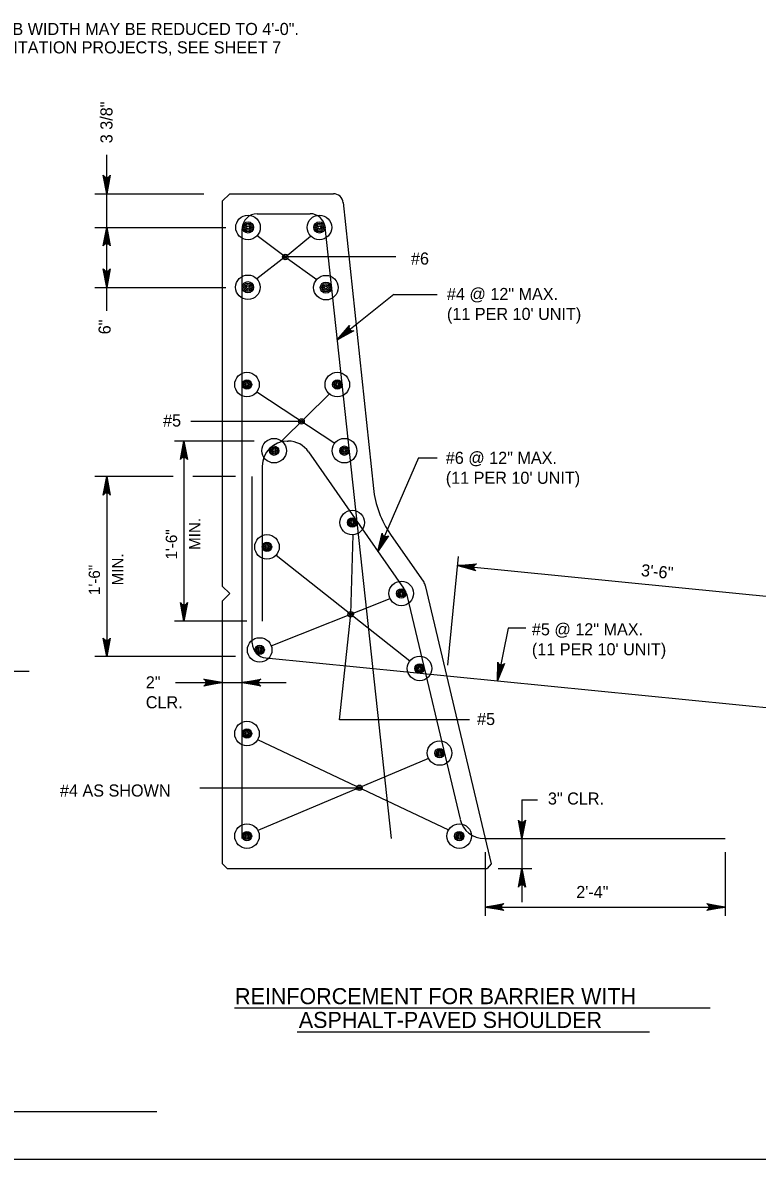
# Model space of a CAD drawing. Extents: x 638167 to 640248, y 296544 to 298920.
# Drawn here: x 638562.8 to 638749.3, y 297153.5 to 297442.2 of the extents above; entities that cross this region are included whole.
import ezdxf

# ---------------------------------------------------------------- set-up
doc = ezdxf.new("R2010")
doc.units = 0
for name, color, linetype in [('1', 7, 'Continuous'), ('50', 7, 'Continuous'), ('57', 7, 'Continuous')]:
    doc.layers.add(name, color=color, linetype=linetype)

# ---------------------------------------------------------------- blocks, each defined once
blk = doc.blocks.new('DIMDOT')
at = {"layer": '57'}
for radius in [2, 1]:
    blk.add_circle((0, 0), radius, dxfattribs=at)
blk = doc.blocks.new('BAR')
at = {"layer": '50'}
for radius in [2, 1.5, 1, 0.5]:
    blk.add_circle((0, 0), radius, dxfattribs=at)

msp = doc.modelspace()

# ---------------------------------------------------------------- linework, layer by layer
at = {"layer": '1'}
for p, q in [((638584.13, 297369), (638584.13, 297408.62)), ((638581.1, 297398.78), (638608.76, 297398.78)), ((638615.37, 297398.78), (638613.46, 297396.88)), ((638615.37, 297398.78), (638641.66, 297398.78)), ((638613.46, 297396.88), (638613.46, 297299.09)), ((638644.18, 297396.51), (638651.84, 297323.92)), ((638622.35, 297393.7), (638635.76, 297393.7)), ((638581.1, 297390.21), (638614.34, 297390.21)), ((638618.54, 297234.95), (638618.54, 297389.89)), ((638639.54, 297390.3), (638656.32, 297234.95)), ((638629.45, 297382.71), (638622.3, 297388.11)), ((638629.47, 297382.74), (638635.9, 297388.01)), ((638629.45, 297382.71), (638622.27, 297377.12)), ((638657.56, 297382.71), (638629.45, 297382.71)), ((638629.45, 297382.71), (638637.43, 297376.99)), ((638581.1, 297374.97), (638614.34, 297374.97)), ((638656.99, 297373.14), (638642.64, 297361.66)), ((638656.99, 297373.14), (638667.99, 297373.14)), ((638622.21, 297348.41), (638642, 297335.39)), ((638628.54, 297335.96), (638640.65, 297347.92)), ((638633.57, 297340.93), (638605.46, 297340.93)), ((638621.59, 297335.92), (638601.3, 297335.92)), ((638603.71, 297335.92), (638603.71, 297290.2)), ((638629.97, 297335.92), (638630.18, 297335.92)), ((638635.39, 297333.2), (638659.49, 297298.6)), ((638623.62, 297329.57), (638623.62, 297290.2)), ((638663.32, 297331.72), (638653, 297307.92)), ((638663.32, 297331.72), (638667.99, 297331.72)), ((638600.98, 297326.9), (638581.1, 297326.9)), ((638584.13, 297326.9), (638584.13, 297281.18)), ((638616.85, 297326.9), (638605.96, 297326.9)), ((638621.08, 297284.63), (638621.08, 297326.9)), ((638646.07, 297291.95), (638646.73, 297312.13)), ((638656.2, 297312.21), (638664.62, 297300.12)), ((638627.1, 297306.95), (638661.09, 297280.08)), ((638670.72, 297279.03), (638673.45, 297306.63)), ((638673.22, 297304.31), (638779.38, 297293.8)), ((638613.46, 297299.09), (638615.37, 297297.18)), ((638665.01, 297299.25), (638681.75, 297228.57)), ((638613.46, 297295.28), (638615.37, 297297.18)), ((638613.46, 297295.28), (638613.46, 297228.6)), ((638625.9, 297283.9), (638656.08, 297295.94)), ((638660.45, 297296.44), (638673.86, 297239.84)), ((638643.24, 297265.1), (638646.07, 297291.95)), ((638619.69, 297290.2), (638601.3, 297290.2)), ((638686.09, 297288.39), (638683.32, 297275.02)), ((638690.52, 297288.39), (638686.09, 297288.39)), ((638616.85, 297281.18), (638581.1, 297281.18)), ((638624.52, 297280.84), (638776.61, 297265.79)), ((638524.47, 297277.5), (638564.39, 297277.5)), ((638601.56, 297274.57), (638629.67, 297274.57)), ((638676.26, 297265.1), (638643.24, 297265.1)), ((638622.44, 297260.08), (638670.93, 297237.14)), ((638665.87, 297255.27), (638622.52, 297237)), ((638607.77, 297247.86), (638648.29, 297247.86)), ((638689.57, 297244.82), (638689.57, 297218.83)), ((638689.57, 297244.82), (638693.48, 297244.82)), ((638680.04, 297234.95), (638741.2, 297234.95)), ((638680.24, 297231.47), (638680.24, 297215.35)), ((638741.2, 297231.47), (638741.2, 297215.35)), ((638613.46, 297228.6), (638614.73, 297227.33)), ((638681.75, 297228.57), (638680.77, 297227.33)), ((638614.73, 297227.33), (638680.77, 297227.33)), ((638683.56, 297227.33), (638692.1, 297227.33)), ((638680.24, 297217.56), (638741.2, 297217.56)), ((638616.56, 297191.93), (638737.34, 297191.93)), ((638632.48, 297185.89), (638721.94, 297185.89)), ((638332.86, 297165.59), (638596.87, 297165.59)), ((638205.78, 297153.48), (638991.78, 297153.48))]:
    msp.add_line(p, q, dxfattribs=at)
for points in [[(638584.13, 297398.78), (638583.24, 297403.48), (638583.37, 297403.3), (638583.5, 297403.12), (638583.65, 297403.03), (638583.81, 297402.93), (638583.97, 297402.91), (638584.13, 297402.88), (638584.28, 297402.91), (638584.44, 297402.93), (638584.6, 297403.03), (638584.76, 297403.12), (638584.88, 297403.3), (638585.01, 297403.48), (638584.13, 297398.78), (638584.88, 297403.3), (638584.76, 297403.12), (638584.13, 297398.78), (638584.6, 297403.03), (638584.44, 297402.93), (638584.13, 297398.78), (638584.28, 297402.91), (638584.13, 297402.88), (638584.13, 297398.78), (638583.97, 297402.91), (638583.81, 297402.93), (638584.13, 297398.78), (638583.65, 297403.03), (638583.5, 297403.12), (638584.13, 297398.78), (638583.37, 297403.3)], [(638584.13, 297390.21), (638585.01, 297385.51), (638584.88, 297385.69), (638584.76, 297385.87), (638584.6, 297385.97), (638584.44, 297386.06), (638584.28, 297386.09), (638584.13, 297386.12), (638583.97, 297386.09), (638583.81, 297386.06), (638583.65, 297385.97), (638583.5, 297385.87), (638583.37, 297385.69), (638583.24, 297385.51), (638584.13, 297390.21), (638583.37, 297385.69), (638583.5, 297385.87), (638584.13, 297390.21), (638583.65, 297385.97), (638583.81, 297386.06), (638584.13, 297390.21), (638583.97, 297386.09), (638584.13, 297386.12), (638584.13, 297390.21), (638584.28, 297386.09), (638584.44, 297386.06), (638584.13, 297390.21), (638584.6, 297385.97), (638584.76, 297385.87), (638584.13, 297390.21), (638584.88, 297385.69)], [(638584.13, 297374.97), (638583.24, 297379.67), (638583.37, 297379.49), (638583.5, 297379.31), (638583.65, 297379.21), (638583.81, 297379.12), (638583.97, 297379.09), (638584.13, 297379.07), (638584.28, 297379.09), (638584.44, 297379.12), (638584.6, 297379.21), (638584.76, 297379.31), (638584.88, 297379.49), (638585.01, 297379.67), (638584.13, 297374.97), (638584.88, 297379.49), (638584.76, 297379.31), (638584.13, 297374.97), (638584.6, 297379.21), (638584.44, 297379.12), (638584.13, 297374.97), (638584.28, 297379.09), (638584.13, 297379.07), (638584.13, 297374.97), (638583.97, 297379.09), (638583.81, 297379.12), (638584.13, 297374.97), (638583.65, 297379.21), (638583.5, 297379.31), (638584.13, 297374.97), (638583.37, 297379.49)], [(638642.64, 297361.66), (638645.75, 297365.28), (638645.69, 297365.07), (638645.63, 297364.86), (638645.65, 297364.68), (638645.68, 297364.5), (638645.76, 297364.36), (638645.83, 297364.22), (638645.95, 297364.11), (638646.07, 297364.01), (638646.24, 297363.94), (638646.42, 297363.88), (638646.63, 297363.89), (638646.85, 297363.91), (638642.64, 297361.66), (638646.63, 297363.89), (638646.42, 297363.88), (638642.64, 297361.66), (638646.24, 297363.94), (638646.07, 297364.01), (638642.64, 297361.66), (638645.95, 297364.11), (638645.83, 297364.22), (638642.64, 297361.66), (638645.76, 297364.36), (638645.68, 297364.5), (638642.64, 297361.66), (638645.65, 297364.68), (638645.63, 297364.86), (638642.64, 297361.66), (638645.69, 297365.07)], [(638603.71, 297335.92), (638604.59, 297331.22), (638604.46, 297331.4), (638604.34, 297331.58), (638604.18, 297331.68), (638604.02, 297331.77), (638603.87, 297331.8), (638603.71, 297331.82), (638603.55, 297331.8), (638603.39, 297331.77), (638603.24, 297331.68), (638603.08, 297331.58), (638602.95, 297331.4), (638602.83, 297331.22), (638603.71, 297335.92), (638602.95, 297331.4), (638603.08, 297331.58), (638603.71, 297335.92), (638603.24, 297331.68), (638603.39, 297331.77), (638603.71, 297335.92), (638603.55, 297331.8), (638603.71, 297331.82), (638603.71, 297335.92), (638603.87, 297331.8), (638604.02, 297331.77), (638603.71, 297335.92), (638604.18, 297331.68), (638604.34, 297331.58), (638603.71, 297335.92), (638604.46, 297331.4)], [(638584.13, 297326.9), (638585.01, 297322.2), (638584.88, 297322.38), (638584.76, 297322.56), (638584.6, 297322.65), (638584.44, 297322.75), (638584.28, 297322.78), (638584.13, 297322.8), (638583.97, 297322.78), (638583.81, 297322.75), (638583.65, 297322.65), (638583.5, 297322.56), (638583.37, 297322.38), (638583.24, 297322.2), (638584.13, 297326.9), (638583.37, 297322.38), (638583.5, 297322.56), (638584.13, 297326.9), (638583.65, 297322.65), (638583.81, 297322.75), (638584.13, 297326.9), (638583.97, 297322.78), (638584.13, 297322.8), (638584.13, 297326.9), (638584.28, 297322.78), (638584.44, 297322.75), (638584.13, 297326.9), (638584.6, 297322.65), (638584.76, 297322.56), (638584.13, 297326.9), (638584.88, 297322.38)], [(638653, 297307.92), (638654.06, 297312.58), (638654.1, 297312.36), (638654.15, 297312.15), (638654.25, 297312), (638654.36, 297311.85), (638654.5, 297311.76), (638654.63, 297311.68), (638654.78, 297311.64), (638654.94, 297311.6), (638655.12, 297311.62), (638655.3, 297311.65), (638655.49, 297311.76), (638655.68, 297311.88), (638653, 297307.92), (638655.49, 297311.76), (638655.3, 297311.65), (638653, 297307.92), (638655.12, 297311.62), (638654.94, 297311.6), (638653, 297307.92), (638654.78, 297311.64), (638654.63, 297311.68), (638653, 297307.92), (638654.5, 297311.76), (638654.36, 297311.85), (638653, 297307.92), (638654.25, 297312), (638654.15, 297312.15), (638653, 297307.92), (638654.1, 297312.36)], [(638673.22, 297304.31), (638677.98, 297304.72), (638677.79, 297304.62), (638677.6, 297304.51), (638677.49, 297304.36), (638677.38, 297304.22), (638677.34, 297304.06), (638677.29, 297303.91), (638677.31, 297303.75), (638677.32, 297303.59), (638677.39, 297303.42), (638677.47, 297303.26), (638677.64, 297303.11), (638677.81, 297302.97), (638673.22, 297304.31), (638677.64, 297303.11), (638677.47, 297303.26), (638673.22, 297304.31), (638677.39, 297303.42), (638677.32, 297303.59), (638673.22, 297304.31), (638677.31, 297303.75), (638677.29, 297303.91), (638673.22, 297304.31), (638677.34, 297304.06), (638677.38, 297304.22), (638673.22, 297304.31), (638677.49, 297304.36), (638677.6, 297304.51), (638673.22, 297304.31), (638677.79, 297304.62)], [(638603.71, 297290.2), (638602.83, 297294.9), (638602.95, 297294.72), (638603.08, 297294.54), (638603.24, 297294.44), (638603.39, 297294.35), (638603.55, 297294.32), (638603.71, 297294.29), (638603.87, 297294.32), (638604.02, 297294.35), (638604.18, 297294.44), (638604.34, 297294.54), (638604.46, 297294.72), (638604.59, 297294.9), (638603.71, 297290.2), (638604.46, 297294.72), (638604.34, 297294.54), (638603.71, 297290.2), (638604.18, 297294.44), (638604.02, 297294.35), (638603.71, 297290.2), (638603.87, 297294.32), (638603.71, 297294.29), (638603.71, 297290.2), (638603.55, 297294.32), (638603.39, 297294.35), (638603.71, 297290.2), (638603.24, 297294.44), (638603.08, 297294.54), (638603.71, 297290.2), (638602.95, 297294.72)], [(638584.13, 297281.18), (638583.24, 297285.87), (638583.37, 297285.69), (638583.5, 297285.51), (638583.65, 297285.42), (638583.81, 297285.33), (638583.97, 297285.3), (638584.13, 297285.27), (638584.28, 297285.3), (638584.44, 297285.33), (638584.6, 297285.42), (638584.76, 297285.51), (638584.88, 297285.69), (638585.01, 297285.87), (638584.13, 297281.18), (638584.88, 297285.69), (638584.76, 297285.51), (638584.13, 297281.18), (638584.6, 297285.42), (638584.44, 297285.33), (638584.13, 297281.18), (638584.28, 297285.3), (638584.13, 297285.27), (638584.13, 297281.18), (638583.97, 297285.3), (638583.81, 297285.33), (638584.13, 297281.18), (638583.65, 297285.42), (638583.5, 297285.51), (638584.13, 297281.18), (638583.37, 297285.69)], [(638683.32, 297275.02), (638683.41, 297279.8), (638683.49, 297279.59), (638683.58, 297279.39), (638683.72, 297279.27), (638683.85, 297279.14), (638684, 297279.09), (638684.15, 297279.03), (638684.31, 297279.02), (638684.47, 297279.02), (638684.64, 297279.08), (638684.81, 297279.14), (638684.97, 297279.29), (638685.13, 297279.44), (638683.32, 297275.02), (638684.97, 297279.29), (638684.81, 297279.14), (638683.32, 297275.02), (638684.64, 297279.08), (638684.47, 297279.02), (638683.32, 297275.02), (638684.31, 297279.02), (638684.15, 297279.03), (638683.32, 297275.02), (638684, 297279.09), (638683.85, 297279.14), (638683.32, 297275.02), (638683.72, 297279.27), (638683.58, 297279.39), (638683.32, 297275.02), (638683.49, 297279.59)], [(638613.46, 297274.57), (638608.76, 297273.69), (638608.94, 297273.82), (638609.13, 297273.94), (638609.22, 297274.1), (638609.31, 297274.26), (638609.34, 297274.42), (638609.37, 297274.57), (638609.34, 297274.73), (638609.31, 297274.89), (638609.22, 297275.05), (638609.13, 297275.2), (638608.94, 297275.33), (638608.76, 297275.45), (638613.46, 297274.57), (638608.94, 297275.33), (638609.13, 297275.2), (638613.46, 297274.57), (638609.22, 297275.05), (638609.31, 297274.89), (638613.46, 297274.57), (638609.34, 297274.73), (638609.37, 297274.57), (638613.46, 297274.57), (638609.34, 297274.42), (638609.31, 297274.26), (638613.46, 297274.57), (638609.22, 297274.1), (638609.13, 297273.94), (638613.46, 297274.57), (638608.94, 297273.82)], [(638618.54, 297274.57), (638623.24, 297275.45), (638623.06, 297275.33), (638622.88, 297275.2), (638622.78, 297275.05), (638622.69, 297274.89), (638622.66, 297274.73), (638622.64, 297274.57), (638622.66, 297274.42), (638622.69, 297274.26), (638622.78, 297274.1), (638622.88, 297273.94), (638623.06, 297273.82), (638623.24, 297273.69), (638618.54, 297274.57), (638623.06, 297273.82), (638622.88, 297273.94), (638618.54, 297274.57), (638622.78, 297274.1), (638622.69, 297274.26), (638618.54, 297274.57), (638622.66, 297274.42), (638622.64, 297274.57), (638618.54, 297274.57), (638622.66, 297274.73), (638622.69, 297274.89), (638618.54, 297274.57), (638622.78, 297275.05), (638622.88, 297275.2), (638618.54, 297274.57), (638623.06, 297275.33)], [(638689.57, 297234.95), (638688.69, 297239.65), (638688.81, 297239.47), (638688.94, 297239.29), (638689.09, 297239.2), (638689.25, 297239.1), (638689.41, 297239.08), (638689.57, 297239.05), (638689.72, 297239.08), (638689.88, 297239.1), (638690.04, 297239.2), (638690.2, 297239.29), (638690.32, 297239.47), (638690.45, 297239.65), (638689.57, 297234.95), (638690.32, 297239.47), (638690.2, 297239.29), (638689.57, 297234.95), (638690.04, 297239.2), (638689.88, 297239.1), (638689.57, 297234.95), (638689.72, 297239.08), (638689.57, 297239.05), (638689.57, 297234.95), (638689.41, 297239.08), (638689.25, 297239.1), (638689.57, 297234.95), (638689.09, 297239.2), (638688.94, 297239.29), (638689.57, 297234.95), (638688.81, 297239.47)], [(638689.57, 297227.33), (638690.45, 297222.64), (638690.32, 297222.82), (638690.2, 297223), (638690.04, 297223.09), (638689.88, 297223.19), (638689.72, 297223.21), (638689.57, 297223.24), (638689.41, 297223.21), (638689.25, 297223.19), (638689.09, 297223.09), (638688.94, 297223), (638688.81, 297222.82), (638688.69, 297222.64), (638689.57, 297227.33), (638688.81, 297222.82), (638688.94, 297223), (638689.57, 297227.33), (638689.09, 297223.09), (638689.25, 297223.19), (638689.57, 297227.33), (638689.41, 297223.21), (638689.57, 297223.24), (638689.57, 297227.33), (638689.72, 297223.21), (638689.88, 297223.19), (638689.57, 297227.33), (638690.04, 297223.09), (638690.2, 297223), (638689.57, 297227.33), (638690.32, 297222.82)], [(638680.24, 297217.56), (638684.93, 297218.44), (638684.75, 297218.32), (638684.57, 297218.19), (638684.48, 297218.04), (638684.39, 297217.88), (638684.36, 297217.72), (638684.33, 297217.56), (638684.36, 297217.41), (638684.39, 297217.25), (638684.48, 297217.09), (638684.57, 297216.93), (638684.75, 297216.81), (638684.93, 297216.68), (638680.24, 297217.56), (638684.75, 297216.81), (638684.57, 297216.93), (638680.24, 297217.56), (638684.48, 297217.09), (638684.39, 297217.25), (638680.24, 297217.56), (638684.36, 297217.41), (638684.33, 297217.56), (638680.24, 297217.56), (638684.36, 297217.72), (638684.39, 297217.88), (638680.24, 297217.56), (638684.48, 297218.04), (638684.57, 297218.19), (638680.24, 297217.56), (638684.75, 297218.32)], [(638741.2, 297217.56), (638736.5, 297216.68), (638736.68, 297216.81), (638736.86, 297216.93), (638736.95, 297217.09), (638737.05, 297217.25), (638737.07, 297217.41), (638737.1, 297217.56), (638737.07, 297217.72), (638737.05, 297217.88), (638736.95, 297218.04), (638736.86, 297218.19), (638736.68, 297218.32), (638736.5, 297218.44), (638741.2, 297217.56), (638736.68, 297218.32), (638736.86, 297218.19), (638741.2, 297217.56), (638736.95, 297218.04), (638737.05, 297217.88), (638741.2, 297217.56), (638737.07, 297217.72), (638737.1, 297217.56), (638741.2, 297217.56), (638737.07, 297217.41), (638737.05, 297217.25), (638741.2, 297217.56), (638736.95, 297217.09), (638736.86, 297216.93), (638741.2, 297217.56), (638736.68, 297216.81)]]:
    msp.add_lwpolyline(points, dxfattribs=at)
for centre in [(638619.99, 297390.21), (638638.12, 297390.21), (638619.97, 297375.01), (638639.77, 297374.92), (638619.73, 297350.3), (638642.67, 297350.3), (638626.62, 297333.5), (638644.48, 297333.5), (638646.45, 297315.24), (638624.81, 297309.06), (638658.91, 297297.24), (638622.95, 297282.87), (638663.56, 297278.17), (638619.73, 297261.63), (638668.65, 297256.68), (638619.73, 297235.59), (638673.64, 297235.59)]:
    msp.add_circle(centre, 3.12, dxfattribs=at)
for centre, radius, start, end in [((638641.66, 297396.24), 2.54, 6.0207, 90), ((638622.35, 297389.89), 3.81, 90, 180), ((638635.76, 297389.89), 3.81, 6.1633, 90), ((638629.97, 297329.57), 6.35, 90, 180), ((638630.18, 297329.57), 6.35, 34.8545, 90), ((638676.78, 297326.55), 25.08, 186.0207, 214.8545), ((638662.54, 297298.67), 2.54, 13.3245, 34.8545), ((638654.28, 297294.98), 6.35, 13.3245, 34.8545), ((638624.89, 297284.63), 3.81, 180, 264.3483), ((638680.04, 297241.3), 6.35, 193.3245, 270)]:
    msp.add_arc(centre, radius, start, end, dxfattribs=at)

# ---------------------------------------------------------------- block references
at = {"layer": '1', "rotation": -90.00000000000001}
for p, xscale, yscale in [((638619.99, 297390.21), 0.714376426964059, 0.714376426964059), ((638638.12, 297390.21), 0.714376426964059, 0.714376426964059), ((638619.97, 297375.01), 0.714376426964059, 0.714376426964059), ((638639.77, 297374.92), 0.714376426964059, 0.714376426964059), ((638619.73, 297350.3), 0.5953136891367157, 0.5953136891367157), ((638642.67, 297350.3), 0.5953136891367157, 0.5953136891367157), ((638626.62, 297333.5), 0.5953136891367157, 0.5953136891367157), ((638644.48, 297333.5), 0.5953136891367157, 0.5953136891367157), ((638646.45, 297315.24), 0.5953136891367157, 0.5953136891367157), ((638624.81, 297309.06), 0.5953136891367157, 0.5953136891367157), ((638658.91, 297297.24), 0.5953136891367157, 0.5953136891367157), ((638622.95, 297282.87), 0.5953136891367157, 0.5953136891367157), ((638663.56, 297278.17), 0.5953136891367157, 0.5953136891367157), ((638619.73, 297261.63), 0.5953136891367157, 0.5953136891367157), ((638668.65, 297256.68), 0.5953136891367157, 0.5953136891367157), ((638619.73, 297235.59), 0.5953136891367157, 0.5953136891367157), ((638673.64, 297235.59), 0.5953136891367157, 0.5953136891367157)]:
    msp.add_blockref('BAR', p, dxfattribs=dict(at, xscale=xscale, yscale=yscale))
at = {"layer": '1', "xscale": 0.349999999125, "yscale": 0.349999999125}
for p in [(638629.45, 297382.71), (638633.57, 297340.93), (638646.07, 297291.95), (638648.29, 297247.86)]:
    msp.add_blockref('DIMDOT', p, dxfattribs=at)

# ---------------------------------------------------------------- texts
at = {"layer": '1'}
for s, height, p in [('MOMENT SLAB WIDTH MAY BE REDUCED TO 4\'-0". ', 3.072, (638533, 297439.1)), ('FOR REHABILITATION PROJECTS, SEE SHEET 7', 3.072, (638533, 297434.43)), ('#6', 3.072, (638661.38, 297380.77)), ('#4 @ 12" MAX.', 3.072, (638670.51, 297371.77)), ("(11 PER 10' UNIT)", 3.072, (638670.51, 297366.7)), ('#5', 3.072, (638598.42, 297339.63)), ('#6 @ 12" MAX.', 3.072, (638670.22, 297330.15)), ("(11 PER 10' UNIT)", 3.072, (638670.22, 297325.08)), ('#5 @ 12" MAX.', 3.072, (638692.09, 297286.58)), ("(11 PER 10' UNIT)", 3.072, (638692.09, 297281.51)), ('2"', 3.072, (638594.03, 297273.11)), ('CLR.', 3.072, (638594.03, 297268.04)), ('#5', 3.072, (638678.17, 297263.8)), ('#4 AS SHOWN', 3.072, (638572.23, 297245.63)), ('3" CLR.', 3.072, (638696.16, 297243.59)), ('2\'-4"', 3.072, (638703.36, 297219.85)), ('REINFORCEMENT FOR BARRIER WITH', 4.08, (638616.69, 297192.88)), ('ASPHALT-PAVED SHOULDER', 4.08, (638632.89, 297186.84))]:
    msp.add_text(s, height=height, dxfattribs=at).set_placement(p)
for s, height, rotation, p in [('3 3/8"', 3.072, 90, (638585.57, 297411.6)), ('6"', 3.072, 90, (638585.1, 297363.06)), ('MIN.', 2.88, 90, (638607.92, 297308.29)), ('1\'-6"', 2.88, 90, (638601.97, 297305.85)), ('MIN.', 2.88, 90, (638588.34, 297299.27)), ('1\'-6"', 2.88, 90, (638582.39, 297296.83)), ('3\'-6"', 3.072, 354.3483, (638719.7, 297301.66))]:
    msp.add_text(s, height=height, rotation=rotation, dxfattribs=at).set_placement(p)

doc.saveas('drawing.dxf')
